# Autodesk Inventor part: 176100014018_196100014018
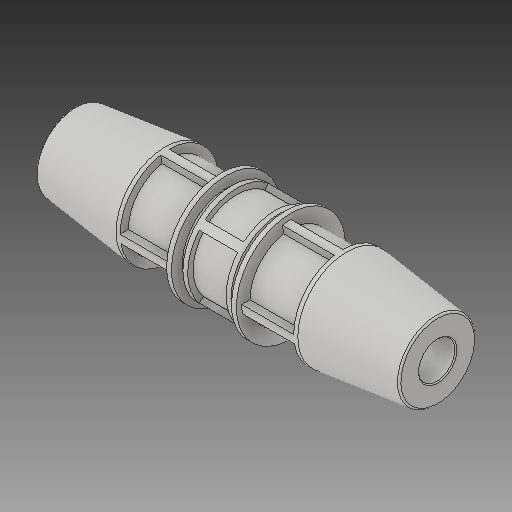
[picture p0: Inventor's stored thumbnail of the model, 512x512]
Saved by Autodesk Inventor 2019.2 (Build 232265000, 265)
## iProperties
Created: 2016-12
Part Number: 176100014018_196100014018
Material: Generic
Description: PLASSON UNIVERSAL SLIP REPAIR COUPLER 14-18 SERIES 17
Document SubType Name: Modeling
Designer: KIM
Mass: 1150.9 g
Surface Area: 2070.91 cm^2
Volume: 1150.9 cm^3
Density: 1 g/cm^3
Appearance: Default
Author: KIM
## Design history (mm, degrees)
derived "17610.ipt"
feature "Solid1::17610.ipt"
tag "TaggingFeature1"
body "Solid1"
other parameters: "d5" = 119, "d11" = 29.75, "d12" = 2.38, "d14" = 45, "d15" = 18, "d16" = 17.64, "d17" = 43.2, "d20" = 40.5, "d21" = 80 deg, "d22" = 25.71429, "d23" = 0, "d25" = 360 deg, "d31" = 23.8, "d32" = 48.6, "d33" = 80 deg, "d34" = 40 deg, "d35" = 43.2, "d36" = 9.52, "d37" = 0, "d39" = 360 deg, "d48" = 0.9, "d52" = 0.54, "d55" = 54, "d58" = 48.6, "d_" = 18, "E_" = 54, "l_" = 119
